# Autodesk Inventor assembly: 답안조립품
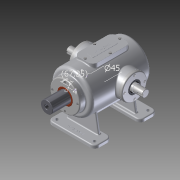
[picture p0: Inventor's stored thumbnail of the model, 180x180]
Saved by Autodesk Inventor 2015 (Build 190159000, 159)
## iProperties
Created: 2016-02
Part Number: 답안조립품
Document SubType Name: Assembly
Designer: Administrator
Mass: 7112.11 g
Surface Area: 4241.85 cm^2
Volume: 1855.5 cm^3
Density: 3.83298 g/cm^3
Author: Administrator
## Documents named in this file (15)
- C:\Users\Administrator\Desktop\360220V1011\답안조립품.iam
- C:\Users\Administrator\Desktop\360220V1011\본체.ipt
- C:\Users\Administrator\Desktop\360220V1011\상부커버.ipt
- C:\Users\Administrator\Desktop\360220V1011\육각머리볼트 M4.ipt
- C:\Users\Administrator\Desktop\360220V1011\축 커버.ipt
- C:\Users\Administrator\Desktop\360220V1011\볼트 M4x0.7.ipt
- C:\Users\Administrator\Desktop\360220V1011\오일실.ipt
- 오일실.ipt
- C:\Users\Administrator\Desktop\360220V1011\베어링 6205.ipt
- 베어링 6205.ipt
- C:\Users\Administrator\Desktop\360220V1011\편심축.ipt
- C:\Users\Administrator\Desktop\360220V1011\슬라이드 커버.ipt
- C:\Users\Administrator\Desktop\360220V1011\부시.ipt
- C:\Users\Administrator\Desktop\360220V1011\가변스프링.ipt
- C:\Users\Administrator\Desktop\360220V1011\슬라이드.ipt
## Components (13 placed, 2 different names)
1. 가변스프링:1
2. M4x0.7:1
3. M4x0.7:2
4. M4x0.7:3
5. M4x0.7:4
6. M4x0.7:5
7. M4x0.7:6
8. M4x0.7:7
9. M4x0.7:8
10. M4x0.7:9
11. M4x0.7:10
12. M4x0.7:11
13. M4x0.7:12
